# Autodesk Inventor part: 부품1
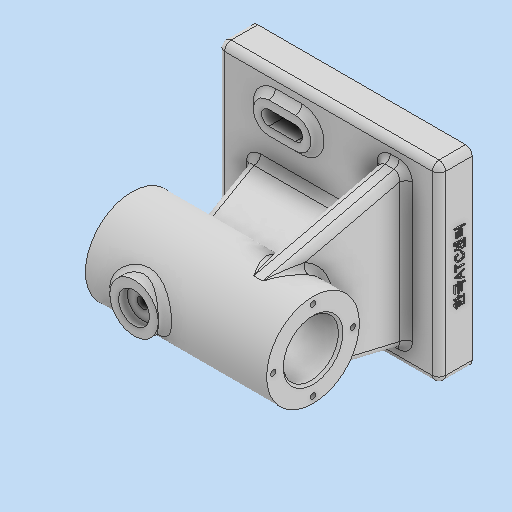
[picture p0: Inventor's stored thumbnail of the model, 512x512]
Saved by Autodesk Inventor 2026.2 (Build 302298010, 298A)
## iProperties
Created: 2026-09
Part Number: 부품1
Material: 알루미늄 6061
Document SubType Name: Modeling
Designer: PC2-02
Density: 2.7 g/cm^3
Appearance: 기본값
Mass: 633.099 g
Surface Area: 512.687 cm^2
Volume: 234.481 cm^3
Author: PC2-02
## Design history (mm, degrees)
sketch "스케치1"
  geometry: L1 (-47, -43)-(47, -43); L2 (50, -40)-(50, 40); L3 (47, 43)-(-47, 43); L4 (-50, 40)-(-50, -40); L5 (-50, -43)-(50, 43); L6 (50, -43)-(-50, 43); A1 r 3 centre (-47, 40) between (-47, 43) and (-50, 40); A2 r 3 centre (47, 40) between (50, 40) and (47, 43); A3 r 3 centre (-47, -40) between (-50, -40) and (-47, -43); A4 r 3 centre (47, -40) between (47, -43) and (50, -40); 1 further point
  constraints: 12 end point, 8 point on circle, 8 point on line, 8 tangent, 4 centre point, 3 equal radius, 2 midpoint, 2 parallel, 1 horizontal, 1 perpendicular
  dimensions: "d0" = 100 distance of L6.end L5.end; "d1" = 86 distance of L5.end L6.start; "d2" = 3 radius of A1
extrude "돌출1" new body sketch "스케치1" stored distance "d3" = 15; taper "d4" = 0 deg
sketch "스케치2"
  geometry: L1 (47, 43)-(-47, 43) reference; L2 (-47, -43)-(47, -43) reference; L3 (50.993, 27)-(-50.993, 27); L4 (-50.993, -27)-(50.993, -27); L5 (0, 60.2)-(0, -60.2) reference; L6 (-75.192, 0)-(94.199, 0) reference; L7 (-50, 40)-(-50, -40) reference; L8 (-24, 40)-(-24, -40); L9 (-24, 27)-(-12, 27); L10 (-24, 23.7)-(-12, 23.7); L11 (-12, 30.3)-(-24, 30.3); L12 (-24, -27)-(-12, -27); L13 (-24, -30.3)-(-12, -30.3); L14 (-12, -23.7)-(-24, -23.7); A1 r 3.3 centre (-24, 27) between (-24, 30.3) and (-24, 23.7); A2 r 3.3 centre (-12, 27) between (-12, 23.7) and (-12, 30.3); A3 r 3.3 centre (-24, -27) between (-24, -23.7) and (-24, -30.3); A4 r 3.3 centre (-12, -27) between (-12, -30.3) and (-12, -23.7); 3 further points
  constraints: 22 end point, 8 point on circle, 8 tangent, 6 point on line, 5 parallel, 4 centre point, 2 midpoint, 1 other
  dimensions: "d5" = 54 distance between parallel lines of L4 L3; "d6" = 26 distance between parallel lines of L7 L8; "d7" = 12 distance of L9.start L9.end; "d8" = 6.6 diameter of A2; "d9" = 6.6 diameter of A4
extrude "돌출2" cut sketch "스케치2" extent not by distance; stored distance "d10" = 0; taper "d11" = 0 deg
sketch "스케치3"
  geometry: L1 (-24, 30.3)-(-12, 30.3) reference; L2 (-12, 23.7)-(-24, 23.7) reference; L3 (-24, -23.7)-(-12, -23.7) reference; L4 (-12, -30.3)-(-24, -30.3) reference; L5 (50, -40)-(50, 40) reference; L6 (47, 43)-(-47, 43) reference; L7 (-50, 40)-(-50, -40) reference; L8 (-47, -43)-(47, -43) reference; L9 (-24, 27)-(-12, 27); L10 (-24, 20)-(-12, 20); L11 (-12, 34)-(-24, 34); L12 (-24, -27)-(-12, -27); L13 (-24, -34)-(-12, -34); L14 (-12, -20)-(-24, -20); A1 r 3.3 centre (-12, 27) between (-12, 23.7) and (-12, 30.3) reference; A2 r 3.3 centre (-24, 27) between (-24, 30.3) and (-24, 23.7) reference; A3 r 3.3 centre (-12, -27) between (-12, -30.3) and (-12, -23.7) reference; A4 r 3.3 centre (-24, -27) between (-24, -23.7) and (-24, -30.3) reference; A5 r 3 centre (47, -40) between (47, -43) and (50, -40) reference; A6 r 3 centre (47, 40) between (50, 40) and (47, 43) reference; A7 r 3 centre (-47, 40) between (-47, 43) and (-50, 40) reference; A8 r 3 centre (-47, -40) between (-50, -40) and (-47, -43) reference; A9 r 7 centre (-24, 27) between (-24, 34) and (-24, 20); A10 r 7 centre (-12, 27) between (-12, 20) and (-12, 34); A11 r 7 centre (-24, -27) between (-24, -20) and (-24, -34); A12 r 7 centre (-12, -27) between (-12, -34) and (-12, -20); 3 further points
  constraints: 16 end point, 8 point on circle, 8 tangent, 4 centre point, 4 parallel, 2 midpoint
  dimensions: "d12" = 14 diameter of A10; "d13" = 14 diameter of A12
extrude "돌출3" join sketch "스케치3" distance "d14" = 3; taper "d15" = 0 deg
sketch "스케치4"
  geometry: L1 (15, 0)-(15, 80) reference; L2 (-57, 0)-(-57, 80); L3 (-96.6, 40)-(33.6, 40) reference; C1 r 21 at (-57, 40); 1 further point
  constraints: 2 end point, 1 centre point, 1 midpoint, 1 parallel, 1 point on line
  dimensions: "d16" = 72 distance between parallel lines of L1 L2; "d17" = 42 diameter of C1
extrude "돌출4" join sketch "스케치4" distance "d18" = 82; taper "d19" = 0 deg
sketch "스케치6"
  geometry: L1 (50, -7.5)-(50, 7.5) reference; L2 (-47, 7.5)-(47, 7.5) reference; L3 (-50, -7.5)-(-50, 7.5) reference; L4 (35, 7.5)-(18.621, 52.5); L5 (-30, 7.5)-(-30, 52.5); L6 (18.621, 52.5)-(-30, 52.5); 1 further point
  constraints: 6 end point, 2 point on line, 1 horizontal, 1 parallel
  dimensions: "d29" = 70 deg angle of L2 L4; "d30" = 15 distance from line of L4.start L1; "d31" = 20 distance between parallel lines of L3 L5; "d33" = 45 vertical distance of L4.start L4.end
extrude "돌출5" join sketch "스케치6" stored distance "d34" = 10; taper "d35" = 0 deg
sketch "스케치7"
  geometry: L1 (-4.814, 20.441)-(57, 35); L2 (-4.814, -20.441)-(57, -35); L3 (72, -43)-(57, -43) reference; L4 (57, 40)-(57, -40) reference; L5 (72, 43)-(57, 43) reference; A1 r 21 centre (0, 0) between (-4.814, -20.441) and (-4.814, 20.441) reference; 1 further point
  constraints: 4 end point, 2 point on circle, 2 point on line, 2 tangent
  dimensions: "d37" = 8 distance from line of L3 L2.end; "d39" = 8 distance of L5.end L1.end
extrude "돌출6" join sketch "스케치7" stored distance "d40" = 10; taper "d41" = 0 deg
node "작업 평면1"
sketch "스케치8"
  geometry: L1 (50, -40)-(50, 40) reference; L2 (-7, -40)-(-7, 40); L3 (-32, 21)-(-32, -21) reference; L4 (-70, 0)-(70, 0) reference; C1 r 11 at (-7, 0); 1 further point
  constraints: 2 end point, 1 centre point, 1 midpoint, 1 parallel, 1 point on line
  dimensions: "d43" = 57 distance between parallel lines of L1 L2; "d44" = 22 diameter of C1
extrude "돌출7" join sketch "스케치8" stored distance "d45" = 10; taper "d46" = 0 deg
sketch "스케치9"
  geometry: C1 r 11 at (0, 0) reference; 2 further points
  constraints: 1 coincident
hole "구멍1" sketch "스케치9" at (0, 0) diameter "d47" = 4.917; stored, may be unused: countersink angle "d51" = 90 deg, drill point angle "d53" = 118 deg; dims "d48" = 12, "d49" = 14, "d50" = 4, "d52" = 17.1
sketch "스케치10"
  geometry: C1 r 21 at (0, 0) reference; C2 r 12.5 at (0, 0); 1 further point
  constraints: 1 centre point, 1 coincident
  dimensions: "d54" = 25 diameter of C2
extrude "돌출8" cut sketch "스케치10" extent not by distance; stored distance "d55" = 0; taper "d56" = 0 deg
sketch "스케치11"
  geometry: C1 r 12.5 at (0, 0) reference; C2 r 14.5 at (0, 0); 1 further point
  constraints: 1 centre point, 1 coincident
  dimensions: "d57" = 29 diameter of C2
extrude "돌출9" cut sketch "스케치11" distance "d58" = 62; taper "d59" = 0 deg
sketch "스케치12" dims "d60" = 36
  geometry: L1 (-91.2, 0)-(43.2, 0) reference; C1 r 21 at (0, 0) reference; 6 further points
  constraints: 1 coincident, 1 horizontal alignment, 1 point on line, 7 other
  dimensions: "d63" = 360 deg dimension on C1.centre point (18, 0) (derived)
hole "구멍2" sketch "스케치12" at (18, 0), (0, 18), (-18, 0), (0, -18) diameter "d65" = 2.459; stored, may be unused: countersink angle "d69" = 90 deg, drill point angle "d71" = 118 deg; dims "d66" = 8, "d67" = 14, "d68" = 4, "d70" = 10
sketch "스케치13" dims "d72" = 36
  geometry: L1 (-43.2, 0)-(91.2, 0) reference; C1 r 12.5 at (0, 0) reference; 6 further points
  constraints: 1 coincident, 1 horizontal alignment, 1 point on line, 7 other
  dimensions: "d75" = 360 deg dimension on C1.centre point (-18, 0) (derived)
hole "구멍3" sketch "스케치13" at (-18, 0), (0, -18), (18, 0), (0, 18) diameter "d77" = 2.459; stored, may be unused: countersink angle "d81" = 90 deg, drill point angle "d83" = 118 deg; dims "d78" = 8, "d79" = 4, "d80" = 2, "d82" = 10
sketch "스케치14"
  geometry: L1 (15, 80)-(15, 0) reference; L2 (-100.2, 40)-(34.2, 40) reference; 2 further points
  constraints: 1 point on line, 1 other
  dimensions: "d84" = 6 distance from line of L1 point (9, 40)
feature "엠보싱1" sketch "스케치14" dims "d85" = 0.5, "d86" = 0
fillet "모깎기1" dims "d87" = 3
chamfer "모따기1" distance "d88" = 1; stored, may be unused: second distance "d89" = 2, angle "d90" = 45 deg
fillet "모깎기2" dims "d91" = 3
node "솔리드1"
node "투영된 루프1"
node "스케치 - 원형 패턴1" dims "d63" = 360 deg (derived)
node "스케치 - 원형 패턴2" dims "d75" = 360 deg (derived)
feature "A9D066F2-1C7D-4E18-AEED-F7BC21143FA4" dims "d47" = 4.917, "d48" = 12, "d49" = 14, "d50" = 4, "d51" = 90 deg, "d52" = 17.1, "d53" = 118 deg
other parameters: "d22" = 5, "d23" = 5, "d42" = 88.5
